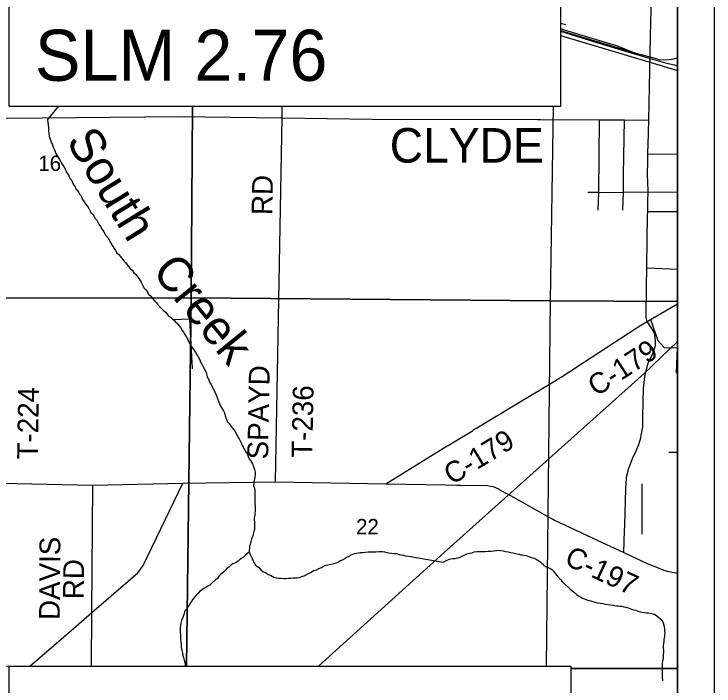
# Model space of a CAD drawing. Extents: x 0 to 34, y 0 to 22.
# Drawn here: x 28.499 to 30.417, y 15.851 to 17.692 of the extents above; entities that cross this region are included whole.
import ezdxf

# ---------------------------------------------------------------- set-up
doc = ezdxf.new("R2010")
doc.units = 0
for name, color, linetype in [('GM_X_City_Street', 7, 'Continuous'), ('GM_X_Corporation_Text', 7, 'Continuous'), ('GM_X_County_Road', 7, 'Continuous'), ('GM_X_County_Road_Text', 7, 'Continuous'), ('GM_X_Minor_River', 7, 'Continuous'), ('GM_X_Minor_River_Text', 7, 'Continuous'), ('GM_X_Rail_Line', 7, 'Continuous'), ('GM_X_Section', 7, 'Continuous'), ('GM_X_Section_Text', 7, 'Continuous'), ('GM_X_Township_Road', 7, 'Continuous'), ('GM_X_Township_Road_Text', 7, 'Continuous'), ('GT_Project_Soil_Layers', 7, 'Continuous'), ('SH_Data', 7, 'Continuous'), ('SH_Text', 7, 'Continuous')]:
    doc.layers.add(name, color=color, linetype=linetype)

msp = doc.modelspace()

# ---------------------------------------------------------------- linework, layer by layer
at = {"layer": 'GM_X_City_Street'}
for p, q in [((30.2352, 17.3091), (30.3167, 17.3081)), ((30.2361, 17.2046), (30.3167, 17.2035)), ((30.2351, 17.1509), (30.3167, 17.1512)), ((30.2325, 16.9964), (30.3167, 16.993)), ((30.3138, 16.7089), (30.3163, 16.7779)), ((30.3138, 16.7089), (30.3167, 16.7088)), ((30.2928, 16.4914), (30.3167, 16.492)), ((30.2202, 16.2673), (30.2195, 16.4052))]:
    msp.add_line(p, q, dxfattribs=at)
msp.add_lwpolyline([(30.2423, 16.8554), (30.2625, 16.7971), (30.2806, 16.7781), (30.3163, 16.7779), (30.3167, 16.7779)], dxfattribs=at)
at = {"layer": 'GM_X_County_Road'}
for p, q in [((30.2382, 17.4012), (30.2399, 17.4918)), ((29.9413, 17.4031), (30.1034, 17.4016)), ((30.2353, 17.313), (30.236, 17.3324)), ((30.1825, 16.8174), (30.2163, 16.8391)), ((30.2163, 16.8391), (30.2333, 16.85)), ((29.9977, 16.697), (30.0401, 16.7247)), ((29.9203, 16.6503), (29.9375, 16.6606)), ((28.9616, 16.4068), (29.2153, 16.4107)), ((29.2153, 16.4107), (29.5177, 16.4051)), ((29.5177, 16.4051), (29.6811, 16.4022)), ((29.6811, 16.4022), (29.7117, 16.4017)), ((29.7117, 16.4017), (29.7219, 16.4015)), ((29.859, 16.3728), (29.9657, 16.3132)), ((30.1694, 16.2174), (30.1719, 16.2773)), ((30.2794, 16.1689), (30.2884, 16.1662)), ((30.2884, 16.1662), (30.3167, 16.1608))]:
    msp.add_line(p, q, dxfattribs=at)
for points in [[(30.2399, 17.4918), (30.2407, 17.5371), (30.2429, 17.6314), (30.2461, 17.7776), (30.2468, 17.8756)], [(27.9854, 17.4096), (28.4819, 17.4065), (28.9512, 17.4111), (29.2332, 17.4075)], [(29.2332, 17.4075), (29.4804, 17.4033), (29.9332, 17.4031), (29.9413, 17.4031)], [(30.1034, 17.4016), (30.1711, 17.4018), (30.2382, 17.4012)], [(30.236, 17.3324), (30.236, 17.3334), (30.2382, 17.4012)], [(30.2351, 17.2925), (30.2351, 17.2944), (30.2352, 17.3091), (30.2353, 17.313)], [(30.2352, 17.2338), (30.2351, 17.2357), (30.2348, 17.2464), (30.2351, 17.2925)], [(30.2351, 17.1548), (30.2352, 17.1577), (30.2354, 17.1794), (30.2361, 17.2046), (30.2352, 17.2338)], [(30.2347, 17.1352), (30.2348, 17.1382), (30.2351, 17.1509), (30.2351, 17.1548)], [(30.2323, 16.9778), (30.2324, 16.9827), (30.2325, 16.9964), (30.2334, 17.0777), (30.2347, 17.1352)], [(30.2317, 16.9385), (30.2322, 16.9632), (30.2323, 16.9778)], [(30.2333, 16.85), (30.2309, 16.8604), (30.2304, 16.8723), (30.2317, 16.9385)], [(30.2333, 16.85), (30.2423, 16.8554), (30.3167, 16.8983)], [(30.2132, 16.5215), (30.2151, 16.5275), (30.2183, 16.5417), (30.2214, 16.5611), (30.222, 16.5897), (30.2222, 16.6284), (30.2231, 16.6657), (30.2273, 16.6992), (30.2362, 16.7367), (30.2494, 16.7612), (30.2565, 16.7835), (30.2565, 16.798), (30.2537, 16.8182), (30.2447, 16.8331), (30.2333, 16.85)], [(30.0401, 16.7247), (30.0409, 16.7252), (30.1825, 16.8174)], [(29.9633, 16.6761), (29.9918, 16.6931), (29.9977, 16.697)], [(29.9375, 16.6606), (29.9435, 16.6643), (29.9633, 16.6761)], [(29.8428, 16.6037), (29.8652, 16.6173), (29.9203, 16.6503)], [(29.7901, 16.5719), (29.8217, 16.591), (29.8333, 16.598), (29.8428, 16.6037)], [(29.7659, 16.5573), (29.7825, 16.5673), (29.7901, 16.5719)], [(29.6885, 16.5104), (29.7254, 16.5327), (29.7547, 16.5505), (29.7572, 16.552)], [(29.7572, 16.552), (29.7581, 16.5525), (29.7659, 16.5573)], [(30.1754, 16.3979), (30.1758, 16.4033), (30.1774, 16.4229), (30.1836, 16.4475), (30.1926, 16.4721), (30.1936, 16.4743), (30.2041, 16.4974), (30.2104, 16.5126), (30.2132, 16.5215)], [(29.5177, 16.4051), (29.686, 16.5089), (29.6885, 16.5104)], [(26.9576, 16.1588), (27.0552, 16.1482), (27.2245, 16.1284), (27.3685, 16.1128), (27.4425, 16.1348), (27.7027, 16.2161), (27.9618, 16.2967), (28.2223, 16.3749), (28.3222, 16.4022), (28.4643, 16.4064), (28.7151, 16.4016), (28.9616, 16.4068)], [(28.7122, 16.0529), (28.8385, 16.1611), (28.8525, 16.1813), (28.9616, 16.4068)], [(29.7219, 16.4015), (29.7965, 16.4002), (29.804, 16.3989), (29.8115, 16.3976), (29.8264, 16.3911), (29.8319, 16.388)], [(30.1719, 16.2773), (30.1724, 16.2906), (30.1748, 16.3914), (30.1754, 16.3979)], [(29.8319, 16.388), (29.8448, 16.3808), (29.859, 16.3728)], [(29.9657, 16.3132), (29.9675, 16.3122), (29.9752, 16.3083)], [(29.9752, 16.3083), (29.98, 16.3059), (30.0962, 16.2503), (30.1694, 16.2174), (30.2358, 16.1862), (30.2576, 16.1775), (30.2674, 16.1735), (30.2745, 16.1706), (30.2758, 16.17), (30.2794, 16.1689)], [(28.5426, 15.9053), (28.6487, 15.9969), (28.7122, 16.0529)]]:
    msp.add_lwpolyline(points, dxfattribs=at)
at = {"layer": 'GM_X_Minor_River'}
for points in [[(28.6198, 17.4387), (28.6197, 17.4384), (28.5909, 17.4026)], [(28.5908, 17.403), (28.5919, 17.3939), (28.5926, 17.389), (28.5936, 17.3787), (28.5935, 17.3723), (28.5942, 17.3639), (28.5956, 17.357), (28.5971, 17.3517), (28.6, 17.3437), (28.6041, 17.3338), (28.6067, 17.3273), (28.6096, 17.3201), (28.6122, 17.3144), (28.6144, 17.3083), (28.6193, 17.301), (28.6237, 17.293), (28.6282, 17.2853), (28.6334, 17.2762), (28.6375, 17.2716), (28.6434, 17.2571), (28.6479, 17.2517), (28.6523, 17.2411), (28.6561, 17.2365), (28.6609, 17.2258), (28.6665, 17.2185), (28.6672, 17.2139), (28.6728, 17.2078), (28.6762, 17.2032), (28.6784, 17.1979), (28.6829, 17.1933), (28.6869, 17.1834), (28.6914, 17.1772), (28.6944, 17.1727), (28.6985, 17.1669), (28.703, 17.1608), (28.7097, 17.1482), (28.7149, 17.1432), (28.7209, 17.1321), (28.7257, 17.1272), (28.7313, 17.1165), (28.7362, 17.1096), (28.7406, 17.1019), (28.7447, 17.0947), (28.7503, 17.0851), (28.7556, 17.0798), (28.7597, 17.0736), (28.7619, 17.0691), (28.7648, 17.0633), (28.7689, 17.0568), (28.773, 17.0496), (28.7768, 17.0442), (28.7805, 17.0377), (28.7861, 17.0331), (28.7932, 17.0243), (28.8003, 17.0159), (28.8052, 17.0101), (28.8093, 17.0048), (28.8172, 16.9945), (28.8224, 16.9906), (28.8273, 16.9833), (28.8318, 16.9791), (28.8355, 16.9745), (28.8411, 16.9669), (28.8445, 16.9619), (28.8475, 16.9569), (28.8497, 16.952), (28.8545, 16.9417), (28.8605, 16.9363), (28.8646, 16.9306), (28.8679, 16.9241), (28.8728, 16.9202), (28.8784, 16.9129), (28.8848, 16.9053), (28.8893, 16.9007), (28.893, 16.8953), (28.8994, 16.8888), (28.9065, 16.8815), (28.9137, 16.8754), (28.9215, 16.8658), (28.9264, 16.8627), (28.9328, 16.8558), (28.9377, 16.8531), (28.9414, 16.8481), (28.9459, 16.845), (28.9515, 16.8378), (28.9549, 16.8328), (28.9597, 16.8251), (28.9631, 16.8202), (28.9668, 16.8141), (28.9709, 16.8083), (28.9739, 16.8018), (28.978, 16.7934), (28.9813, 16.7873), (28.985, 16.7801), (28.9906, 16.7736), (28.9962, 16.7644), (29, 16.7587), (29.0033, 16.7526), (29.0078, 16.7449), (29.0103, 16.7381), (29.0144, 16.7312)], [(29.0144, 16.7312), (29.0178, 16.7236), (29.0219, 16.7174), (29.0252, 16.7109), (29.0285, 16.6976), (29.0318, 16.6915), (29.0355, 16.6816), (29.0389, 16.677), (29.0411, 16.6721), (29.0448, 16.6663), (29.0478, 16.6595), (29.0507, 16.6537), (29.0537, 16.6461), (29.0562, 16.6389), (29.0588, 16.6313), (29.0621, 16.6248), (29.0647, 16.6175), (29.0685, 16.6118), (29.0729, 16.6045), (29.0755, 16.5992), (29.0777, 16.5908), (29.0792, 16.5859), (29.081, 16.5813), (29.0836, 16.5748), (29.0881, 16.5702), (29.0933, 16.5626), (29.0978, 16.5576), (29.1027, 16.5511), (29.1086, 16.5408), (29.1138, 16.5308), (29.1175, 16.5247), (29.1205, 16.519), (29.1264, 16.5053), (29.1309, 16.4988), (29.1339, 16.493), (29.1383, 16.485), (29.1405, 16.4801), (29.1435, 16.4739), (29.1472, 16.4686), (29.1521, 16.4598), (29.1554, 16.4526), (29.158, 16.4442), (29.1601, 16.4366), (29.1601, 16.4309), (29.1589, 16.4237), (29.1557, 16.41), (29.1552, 16.4009), (29.1574, 16.3933), (29.1592, 16.3876), (29.1591, 16.3766), (29.1586, 16.3713), (29.1584, 16.3527), (29.1595, 16.3428), (29.1601, 16.336), (29.1597, 16.3299), (29.1592, 16.325), (29.1588, 16.3204), (29.158, 16.3151), (29.1572, 16.3106), (29.1582, 16.2958), (29.1581, 16.2874), (29.1576, 16.2798), (29.1556, 16.2741), (29.1521, 16.2598), (29.1493, 16.2545), (29.1477, 16.2473), (29.1457, 16.2389), (29.1442, 16.2344), (29.1441, 16.2299), (29.1429, 16.2246), (29.1432, 16.2192), (29.1462, 16.2116), (29.1484, 16.2063), (29.1514, 16.2005), (29.154, 16.1944), (29.1558, 16.1899), (29.1607, 16.1822), (29.1697, 16.1757), (29.1753, 16.1699), (29.1809, 16.1653), (29.1904, 16.1603), (29.1964, 16.1564), (29.2021, 16.1548), (29.2107, 16.1498), (29.2183, 16.1478), (29.2236, 16.147), (29.23, 16.1466), (29.2372, 16.1457), (29.2448, 16.146), (29.2505, 16.1471), (29.257, 16.147), (29.2642, 16.1473), (29.2741, 16.1476), (29.2809, 16.1483), (29.2889, 16.152), (29.2935, 16.1535), (29.3042, 16.159), (29.3114, 16.162), (29.3206, 16.168), (29.3274, 16.1698), (29.3343, 16.1728)], [(29.143, 16.2183), (29.1402, 16.2162), (29.1329, 16.2099), (29.1275, 16.2042), (29.1226, 16.2005), (29.118, 16.1975), (29.1134, 16.1934), (29.1076, 16.19), (29.0989, 16.1855), (29.0931, 16.1822), (29.0878, 16.1769), (29.0832, 16.1739), (29.0778, 16.1675), (29.0728, 16.1634), (29.0655, 16.1574), (29.0606, 16.1529), (29.0563, 16.1461), (29.051, 16.142), (29.0418, 16.1338), (29.0352, 16.1278), (29.0303, 16.1244), (29.0245, 16.121), (29.0188, 16.1181), (29.0119, 16.1128), (29.0073, 16.1098), (29.0035, 16.1049), (28.9985, 16.1008), (28.9943, 16.0952), (28.9893, 16.0888), (28.9839, 16.0816), (28.9804, 16.0763), (28.9758, 16.0692), (28.9727, 16.0631), (28.9673, 16.0575), (28.9649, 16.0503), (28.9622, 16.042), (28.9602, 16.0371), (28.9583, 16.031), (28.9559, 16.0235), (28.9551, 16.0166), (28.9543, 16.0113), (28.9538, 16.0034), (28.9541, 15.9988), (28.9552, 15.9927), (28.9547, 15.9878), (28.9554, 15.9802), (28.9561, 15.9714), (28.9568, 15.9654), (28.9574, 15.9578), (28.9585, 15.9486), (28.9603, 15.9414), (28.9617, 15.9349), (28.9636, 15.9292), (28.965, 15.922), (28.9679, 15.9121), (28.9678, 15.906), (28.968, 15.9053)], [(29.3343, 16.1728), (29.3411, 16.1761), (29.3465, 16.1791), (29.3545, 16.1824), (29.3716, 16.1857), (29.3792, 16.1879), (29.3842, 16.1897), (29.3937, 16.1953), (29.399, 16.1971), (29.4055, 16.2005), (29.4101, 16.2038), (29.4155, 16.2061), (29.4204, 16.2094), (29.4269, 16.2128), (29.4315, 16.2142), (29.4379, 16.2153), (29.4471, 16.2171), (29.4543, 16.217), (29.4611, 16.2177), (29.4691, 16.2188), (29.4752, 16.2191), (29.4824, 16.2186), (29.4899, 16.2189), (29.4998, 16.2196), (29.5074, 16.2195), (29.5138, 16.2187), (29.5207, 16.2171), (29.5252, 16.2163), (29.5331, 16.2154), (29.5407, 16.2146), (29.5472, 16.2138), (29.554, 16.2118), (29.5593, 16.2106), (29.5649, 16.2094), (29.5714, 16.2082), (29.5801, 16.2073), (29.6747, 16.1908)], [(29.6747, 16.1908), (29.6911, 16.1991), (29.701, 16.2003), (29.7075, 16.2004), (29.7113, 16.2019), (29.7185, 16.2034), (29.7253, 16.2061), (29.7325, 16.21), (29.7393, 16.2134), (29.7469, 16.2154), (29.7537, 16.2165), (29.7598, 16.2185), (29.767, 16.22), (29.7734, 16.22), (29.7799, 16.2197), (29.784, 16.2193), (29.7897, 16.2201), (29.7969, 16.2209), (29.8061, 16.221), (29.8136, 16.2214), (29.8205, 16.2225), (29.8265, 16.223), (29.833, 16.2226), (29.8391, 16.2215), (29.8452, 16.22), (29.8528, 16.2185), (29.86, 16.2174), (29.8661, 16.2163), (29.8702, 16.2148), (29.8778, 16.2137), (29.8824, 16.2122), (29.8873, 16.2107), (29.8911, 16.2103), (29.8953, 16.21), (29.901, 16.2085), (29.9063, 16.207), (29.9113, 16.2055), (29.917, 16.2033), (29.9238, 16.201), (29.9295, 16.1984), (29.9337, 16.1957), (29.9391, 16.192), (29.9452, 16.1871), (29.949, 16.1848), (29.9501, 16.181), (29.957, 16.1776), (29.9669, 16.1739), (29.9722, 16.1701), (29.9768, 16.1659), (29.9814, 16.1595), (29.9859, 16.1538), (29.9901, 16.1493), (29.9959, 16.1429), (30.0016, 16.1368), (30.0065, 16.1323), (30.01, 16.1285), (30.0184, 16.1209), (30.0226, 16.1168), (30.0264, 16.1134), (30.031, 16.11), (30.0348, 16.107), (30.0412, 16.1013), (30.0454, 16.0979), (30.0515, 16.0945), (30.0565, 16.0922), (30.0633, 16.0892), (30.0686, 16.0877), (30.074, 16.0859), (30.0789, 16.0844), (30.0846, 16.0825), (30.0915, 16.081), (30.0979, 16.0795), (30.1051, 16.078), (30.112, 16.0769), (30.1196, 16.0754), (30.1268, 16.0743), (30.1329, 16.0732), (30.1405, 16.0725), (30.1496, 16.071), (30.1538, 16.0707), (30.1587, 16.0703), (30.1636, 16.0696), (30.1701, 16.0681), (30.1758, 16.067), (30.1815, 16.0655), (30.191, 16.0621), (30.1963, 16.0602), (30.2024, 16.0587), (30.2066, 16.0576), (30.2146, 16.0542), (30.226, 16.0528), (30.2313, 16.0517), (30.2374, 16.0513), (30.2415, 16.051), (30.2453, 16.0498), (30.2495, 16.0491), (30.2556, 16.0468), (30.2606, 16.0427), (30.2648, 16.0397), (30.2712, 16.0344), (30.2739, 16.0306)], [(30.2739, 16.0306), (30.2762, 16.0268), (30.2781, 16.0211), (30.2797, 16.0147), (30.2809, 16.0078), (30.2813, 16.0037), (30.2817, 15.9972), (30.2809, 15.9915), (30.281, 15.9866), (30.2795, 15.9786), (30.2788, 15.9725), (30.278, 15.9676), (30.2777, 15.9622), (30.2777, 15.9558), (30.2781, 15.9482), (30.2782, 15.9425), (30.2778, 15.9379), (30.2774, 15.9322), (30.2771, 15.9269), (30.2756, 15.9201), (30.2745, 15.9132), (30.2745, 15.9068), (30.2749, 15.903), (30.275, 15.8984), (30.2746, 15.8912), (30.2743, 15.8843), (30.2743, 15.8741), (30.2755, 15.8692), (30.2759, 15.8654)]]:
    msp.add_lwpolyline(points, dxfattribs=at)
at = {"layer": 'GM_X_Rail_Line'}
msp.add_line((29.9962, 17.6667), (30.0102, 17.6629), dxfattribs=at)
for points in [[(30.1938, 17.5871), (30.15, 17.6045), (30.0073, 17.6475), (29.9962, 17.6509)], [(29.9962, 17.6468), (30.0968, 17.6161), (30.1816, 17.5905), (30.1938, 17.5871)], [(29.9962, 17.6443), (30.0961, 17.6139), (30.1809, 17.5882), (30.2417, 17.57), (30.2742, 17.5607), (30.2911, 17.5565), (30.3085, 17.5522), (30.3167, 17.5497)], [(29.9962, 17.633), (30.2412, 17.5602), (30.3167, 17.5371)], [(30.1938, 17.5871), (30.2612, 17.5686), (30.2652, 17.5675), (30.2871, 17.5658), (30.307, 17.5691), (30.3167, 17.5715)], [(29.3336, 15.9053), (29.6776, 16.2169), (30.2251, 16.707), (30.3167, 16.7947)]]:
    msp.add_lwpolyline(points, dxfattribs=at)
at = {"layer": 'GM_X_Section'}
for points in [[(28.9884, 17.4387), (28.9846, 16.9148), (27.9749, 16.9131), (27.9928, 17.9132), (28.4862, 17.9139)], [(29.976, 17.4387), (29.9677, 16.9066), (30.3167, 16.9046), (30.3167, 17.9232), (29.9962, 17.9263)], [(29.976, 17.4387), (29.9677, 16.9066), (28.9846, 16.9148), (28.9884, 17.4387)], [(28.4862, 15.9049), (27.9584, 15.9108), (27.9749, 16.9131), (28.9846, 16.9148), (28.9715, 15.9053)], [(28.9715, 15.9053), (28.9846, 16.9148), (29.9677, 16.9066), (29.9569, 15.9053)], [(30.0249, 15.8995), (30.3167, 15.899), (30.3167, 16.9046), (29.9677, 16.9066), (29.9569, 15.9053)], [(29.9522, 15.2053), (29.9501, 14.8885), (30.3167, 14.8883), (30.3167, 15.899), (30.0249, 15.8995)]]:
    msp.add_lwpolyline(points, dxfattribs=at)
at = {"layer": 'GM_X_Township_Road'}
msp.add_line((30.0713, 17.2042), (30.1002, 17.2038), dxfattribs=at)
for points in [[(29.2153, 16.4107), (29.2332, 17.4075), (29.2337, 17.4387)], [(30.0996, 17.1541), (30.1011, 17.2038), (30.1034, 17.4016)], [(30.1687, 17.2338), (30.1688, 17.2516), (30.1711, 17.4018)], [(30.1673, 17.1545), (30.1685, 17.2042), (30.1687, 17.2338)], [(30.1002, 17.2038), (30.1011, 17.2038), (30.1336, 17.203), (30.1685, 17.2042), (30.2361, 17.2046)], [(28.7109, 15.9053), (28.7122, 16.0529), (28.7151, 16.4016)]]:
    msp.add_lwpolyline(points, dxfattribs=at)
at = {"layer": 'GT_Project_Soil_Layers'}
for q in [(28.9364, 16.8538), (28.9867, 16.72)]:
    msp.add_line((28.9802, 16.8559), q, dxfattribs=at)
at = {"layer": 'SH_Data'}
for points in [[(23.4167, 21), (30.4167, 21), (30.4167, 14), (23.4167, 14)], [(23.5167, 20.9), (30.3167, 20.9), (30.3167, 14.1), (23.5167, 14.1)], [(28.4862, 18.1387), (29.9962, 18.1387), (29.9962, 17.4387), (28.4862, 17.4387)], [(28.4862, 15.9053), (30.0249, 15.9053), (30.0249, 15.2053), (28.4862, 15.2053)]]:
    msp.add_lwpolyline(points, close=True, dxfattribs=at)

# ---------------------------------------------------------------- texts
at = {"layer": 'GM_X_Corporation_Text'}
msp.add_text('CLYDE', height=0.0947, rotation=0, dxfattribs=at).set_placement((29.5283, 17.2846))
at = {"layer": 'GM_X_County_Road_Text'}
for s, rotation, p in [('C-179', 33.1867, (30.0947, 16.6427)), ('C-179', 31.4252, (29.6987, 16.4007)), ('C-197', 335.0307, (30.0038, 16.1855))]:
    msp.add_text(s, height=0.05682, rotation=rotation, dxfattribs=at).set_placement(p)
at = {"layer": 'GM_X_Minor_River_Text'}
for s, rotation, p in [('South', 301.6846, (28.6402, 17.3435)), ('Creek', 309.0764, (28.8745, 16.9861))]:
    msp.add_text(s, height=0.09474, rotation=rotation, dxfattribs=at).set_placement(p)
at = {"layer": 'GM_X_Section_Text'}
for s, p in [('16', (28.5657, 17.262)), ('22', (29.4361, 16.2669))]:
    msp.add_text(s, height=0.04186, rotation=0, dxfattribs=at).set_placement(p)
at = {"layer": 'GM_X_Township_Road_Text'}
for s, rotation, p in [('RD', 89.0128, (29.2067, 17.1407)), ('SPAYD', 88.9513, (29.195, 16.4716)), ('T-224', 89.1579, (28.5643, 16.4714)), ('T-236', 88.8773, (29.316, 16.4759)), ('DAVIS', 89.5493, (28.6242, 16.0319)), ('RD', 89.5045, (28.69, 16.0889))]:
    msp.add_text(s, height=0.05682, rotation=rotation, dxfattribs=at).set_placement(p)
at = {"layer": 'SH_Text'}
msp.add_text('SLM 2.76', height=0.14, dxfattribs=at).set_placement((28.5562, 17.5087))

doc.saveas('drawing.dxf')
